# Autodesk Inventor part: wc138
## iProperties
Shininess: 64.0
Length Units: 11272
Angle Units: 11279
Time Units: 11290
Mass Units: 11286
Length Display Precision: 3
Angle Display Precision: 2
Compacted: True
Part Number: wc138
Document SubType Name: Modeling
Created: 2004-08
Designer: John Blackburn
Manufacturer: Standard
Standards Organization: Custom
Density: 0.0
Volumn: 0.0
Area: 0.0
PropertySet Name: Model Information
Control State: 0
Master: False
Checked Out: False
Author: John Blackburn
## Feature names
1. Base1
